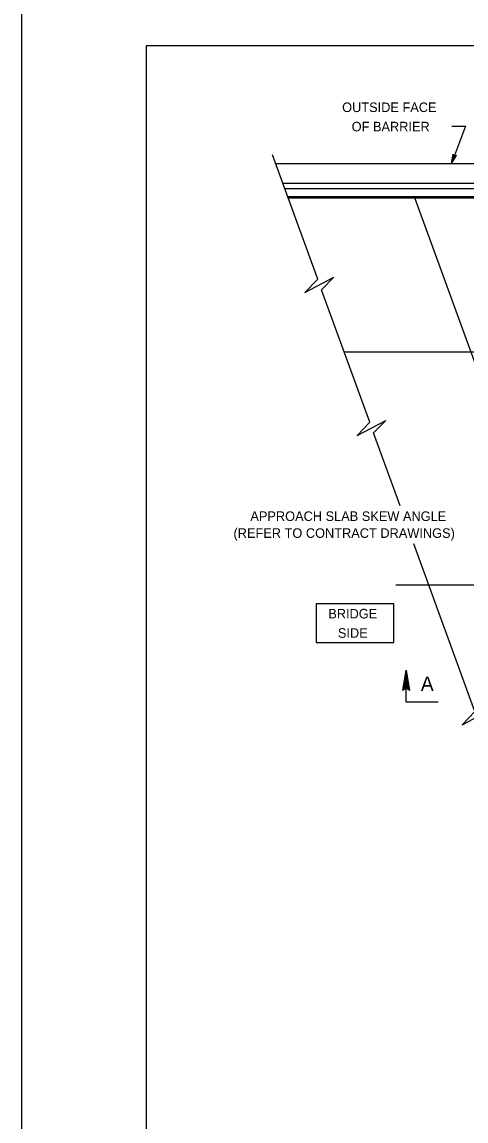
# Model space of a CAD drawing. Extents: x 2084213 to 2099800, y 976677 to 981262.
# Drawn here: x 2094075 to 2094533, y 977470 to 978601 of the extents above; entities that cross this region are included whole.
import ezdxf

# ---------------------------------------------------------------- set-up
doc = ezdxf.new("R2010")
doc.units = 0
doc.layers.add('1', color=7, linetype='Continuous')
doc.layers.add('PLT-BNDY', color=7, linetype='Continuous')

msp = doc.modelspace()

# ---------------------------------------------------------------- linework, layer by layer
at = {"layer": '1'}
for p, q in [((2094532.1, 978494), (2094517.6, 978455.6)), ((2094517.9, 978494), (2094532.1, 978494)), ((2094379.8, 978336.5), (2094333.2, 978464.5)), ((2094336.4, 978455.6), (2094676.6, 978455.6)), ((2094341, 978455.6), (2094574.4, 978455.6)), ((2094343.7, 978435.6), (2094678.8, 978435.6)), ((2094345.7, 978430), (2094574.4, 978430)), ((2094348.7, 978421.8), (2094574.4, 978421.8)), ((2094349.3, 978420.2), (2095284.3, 978420.2)), ((2094769.8, 977623.5), (2094479.9, 978420.2)), ((2094433.4, 978189.2), (2094383.7, 978325.7)), ((2094406.9, 978261.8), (2095284.3, 978261.8)), ((2094464.7, 978103.1), (2094437.3, 978178.4)), ((2094541.7, 977891.5), (2094478.9, 978064.1)), ((2094460.1, 978021.8), (2094987.1, 978021.8))]:
    msp.add_line(p, q, dxfattribs=at)
for points in [[(2096781.6, 976726.5), (2096781.6, 978576.9), (2094202.9, 978576.9), (2094202.9, 976726.5), (2096781.6, 976726.5), (2096781.6, 976812.9), (2096125.4, 976812.9), (2096125.4, 977025.1), (2096781.6, 977025.1), (2096781.6, 977120.2), (2096125.4, 977120.2), (2096125.4, 976726.5), (2096384, 976726.5), (2096384, 976812.9), (2096384, 976726.5), (2096636.6, 976726.5), (2096636.6, 976812.9), (2096636.6, 976772.5), (2096781.6, 976772.5)], [(2094517.6, 978455.6), (2094522.7, 978464.1), (2094522.3, 978463.8), (2094522, 978463.6), (2094521.6, 978463.5), (2094521.2, 978463.5), (2094520.9, 978463.5), (2094520.6, 978463.6), (2094520.3, 978463.7), (2094520, 978463.9), (2094519.8, 978464.2), (2094519.5, 978464.5), (2094519.4, 978465), (2094519.3, 978465.4), (2094517.6, 978455.6), (2094519.4, 978465), (2094519.5, 978464.5), (2094517.6, 978455.6), (2094519.8, 978464.2), (2094520, 978463.9), (2094517.6, 978455.6), (2094520.3, 978463.7), (2094520.6, 978463.6), (2094517.6, 978455.6), (2094520.9, 978463.5), (2094521.2, 978463.5), (2094517.6, 978455.6), (2094521.6, 978463.5), (2094522, 978463.6), (2094517.6, 978455.6), (2094522.3, 978463.8)], [(2094379.8, 978336.5), (2094366.6, 978322.9), (2094396.4, 978338.5), (2094383.7, 978325.6)], [(2094433.4, 978189.2), (2094420.2, 978175.6), (2094450, 978191.2), (2094437.3, 978178.4)], [(2094468.5, 977913.9), (2094469.9, 977914.7), (2094471, 977933.9), (2094468.5, 977913.9), (2094467.6, 977912.9), (2094471, 977933.9), (2094471.9, 977914.7), (2094473.3, 977914), (2094471, 977933.9), (2094474.3, 977912.9), (2094473.3, 977914)], [(2094504, 977900.9), (2094471, 977900.9), (2094471, 977933.9)], [(2094541.7, 977891.5), (2094528.6, 977877.8), (2094558.3, 977893.4), (2094545.7, 977880.6)]]:
    msp.add_lwpolyline(points, dxfattribs=at)
msp.add_lwpolyline([(2094378.2, 977962.3), (2094458.2, 977962.3), (2094458.2, 978002.3), (2094378.2, 978002.3)], close=True, dxfattribs=at)
at = {"layer": 'PLT-BNDY'}
msp.add_lwpolyline([(2094074.9, 978626.1), (2096834.1, 978626.1), (2096834.1, 976677.3), (2094074.9, 976677.3)], close=True, dxfattribs=at)

# ---------------------------------------------------------------- texts
at = {"layer": '1'}
for s, height, p in [('OUTSIDE FACE', 9.843, (2094404.9, 978508.7)), ('OF BARRIER', 9.84, (2094414.7, 978488.8)), ('APPROACH SLAB SKEW ANGLE', 9.843, (2094310.3, 978087.6)), ('(REFER TO CONTRACT DRAWINGS)', 9.843, (2094292.9, 978070.2)), ('BRIDGE', 9.84, (2094390.6, 977987.2)), ('SIDE', 9.84, (2094400.5, 977967.3)), ('A', 14.8, (2094486, 977912.6))]:
    msp.add_text(s, height=height, dxfattribs=at).set_placement(p)

doc.saveas('drawing.dxf')
